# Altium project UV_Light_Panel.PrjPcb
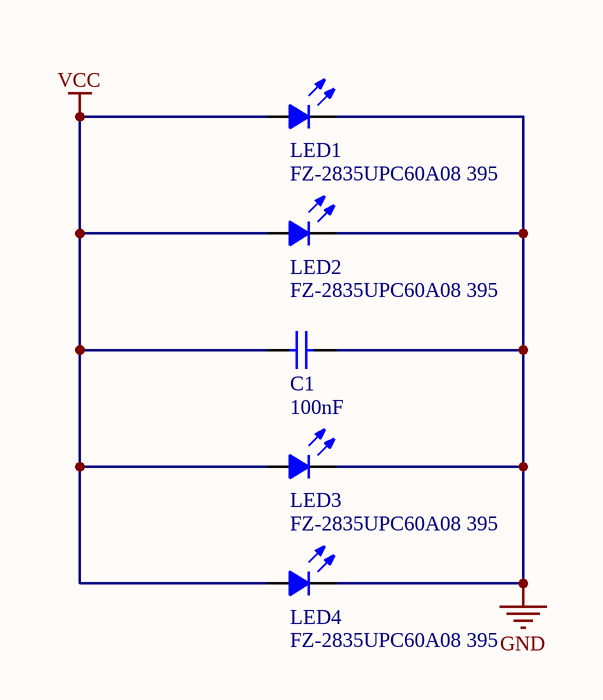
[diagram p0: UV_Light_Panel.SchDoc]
CAGE_CODE: ?????; CONTRACT_NUMBER: <CONTRACT NO>; DOC_NO_ASSY_DWG: <ASSY DWG NO>; DOC_NO_BOM: <BOM DOC NO>; DOC_NO_FAB_DWG: <FAB DWG NO>; DOC_NO_SCH_DWG: <SCH DWG NO>; PCB_2_DEC_TOL: +/-.01; PCB_3_DEC_TOL: +/-.010; PCB_ANG_TOL: +/-1/2; PCB_ASSEMBLY_NO: <PCB ASSY NO>; PCB_CHECKER: - -----; PCB_CHECKER_APP_DATE: --/--/----; PCB_DESIGNER: - -----; PCB_DESIGNER_APP_DATE: --/--/----; PCB_DWG_NO: <PCB DWG NO>; PCB_ENGINEER: - -----; PCB_ENGINEER_APP_DATE: --/--/----; PCB_PART_NUMBER: <PCB PN>; PCB_REV: A; SCH_REV: A
1 sheet, 5 parts. Net scope: global (net labels, ports and power ports of the same name join across sheets).
Board file: UV_Light_Panel.PcbDoc

## Sheet UV_Light_Panel.SchDoc
size A4; SheetNumber: 1; SheetTotal: 1; ENG_APP_DATE: --/--/--; DSN_APP_DATE: --/--/--; CHK_APP_DATE: --/--/--

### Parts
C1  value 100nF  [C 0603(1608)100_L]  (hidden comment: CL10B104KB8NNNC)
LED1  FZ-2835UPC60A08 395  [LED 2835]
LED2  FZ-2835UPC60A08 395  [LED 2835]
LED3  FZ-2835UPC60A08 395  [LED 2835]
LED4  FZ-2835UPC60A08 395  [LED 2835]

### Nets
GND: C1.2 LED1.2(K) LED2.2(K) LED3.2(K) LED4.2(K)
VCC: C1.1 LED1.1(A) LED2.1(A) LED3.1(A) LED4.1(A)

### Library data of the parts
C1 = CMP-001-00085-2: Multi Layer Ceramic Capacitor (MLCC) / Cap Ceramic 0.1uF 50V X7R 10% Pad SMD 0603 125¡ãC T/R
LED1-LED4 = CMP-007-00089-2: PLCC 2835 Purple LED 395NM; Colour: UV; Luminous Intensity(IF =60mA): 30Mcd; Forward Current: 60mA; Viewing Angle(IF =60mA): 120deg; Reverse Current Max(VR=5V): 10uA; Max Power Dissipation: 200mW; Forward Voltage: 3.4V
